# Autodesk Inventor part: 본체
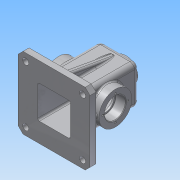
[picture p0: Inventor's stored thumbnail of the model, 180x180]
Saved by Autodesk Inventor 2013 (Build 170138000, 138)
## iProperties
Created: 2018-10
Part Number: 본체
Material: 알루미늄 6061
Document SubType Name: Modeling
Designer: Administrator
Density: 2.71 g/cm^3
Mass: 797.27 g
Surface Area: 899.907 cm^2
Volume: 294.196 cm^3
Author: Administrator
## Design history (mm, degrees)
sketch "스케치1"
  geometry: L1 (32.5, -32.5)-(-32.5, -32.5); L2 (-32.5, -32.5)-(-32.5, 32.5); L3 (-32.5, 32.5)-(32.5, 32.5); L4 (32.5, 32.5)-(32.5, -32.5); L5 (32.5, -32.5)-(-32.5, 32.5); L6 (-32.5, -32.5)-(32.5, 32.5); 1 further point
  constraints: 12 end point, 2 midpoint, 2 parallel, 1 horizontal, 1 perpendicular
  dimensions: "d0" = 65 distance of L2.end L3.end; "d1" = 65 distance of L1.end L2.end
extrude "돌출1" new body sketch "스케치1" distance "d2" = 55; taper "d4" = 0 deg; dims "d3" = 55, "d5" = 0
feature "쉘1" dims "d6" = 5
fillet "모깎기2" dims "d8" = 3
node "작업 평면1"
sketch "스케치2"
  geometry: C1 r 20 at (0, 0); 1 further point
  constraints: 1 centre point, 1 coincident
  dimensions: "d10" = 40 diameter of C1
extrude "돌출2" join sketch "스케치2" stored distance "d11" = 55; taper "d12" = 7 deg
hole "구멍1" diameter "d15" = 22.835; stored, may be unused: countersink angle "d19" = 90 deg, drill point angle "d21" = 118 deg; dims "d13" = 10, "d14" = 10, "d16" = 50, "d17" = 4, "d18" = 2, "d20" = 50
sketch "스케치3"
  geometry: L1 (-32.5, -32.5)-(32.5, -32.5) reference; L2 (32.5, -32.5)-(32.5, 32.5) reference; L3 (32.5, 32.5)-(-32.5, 32.5) reference; L4 (-32.5, 32.5)-(-32.5, -32.5) reference; L5 (60, -60)-(-60, -60); L6 (-60, -60)-(-60, 60); L7 (-60, 60)-(60, 60); L8 (60, 60)-(60, -60); L9 (60, -60)-(-60, 60); L10 (-60, -60)-(60, 60); A1 r 8 centre (24.5, -24.5) between (24.5, -32.5) and (32.5, -24.5) reference; A2 r 8 centre (24.5, 24.5) between (32.5, 24.5) and (24.5, 32.5) reference; A3 r 8 centre (-24.5, 24.5) between (-24.5, 32.5) and (-32.5, 24.5) reference; A4 r 8 centre (-24.5, -24.5) between (-32.5, -24.5) and (-24.5, -32.5) reference; 1 further point
  constraints: 12 end point, 2 midpoint, 2 parallel, 1 horizontal, 1 perpendicular
  dimensions: "d22" = 120 distance of L6.end L7.end; "d23" = 120 distance of L5.end L6.end
extrude "돌출3" join sketch "스케치3" distance "d24" = 10; taper "d25" = 0 deg
chamfer "모따기1" distance "d26" = 8; stored, may be unused: second distance "d27" = 2, angle "d28" = 45 deg
sketch "스케치4"
  geometry: L1 (-60, 52)-(-60, -52) reference; L2 (52, 60)-(-52, 60) reference; C1 r 5 at (-47.5, 47.5); 1 further point
  constraints: 1 centre point
  dimensions: "d29" = 10 diameter of C1; "d30" = 12.5 distance from line of C1.centre L1; "d31" = 12.5 distance from line of C1.centre L2
extrude "돌출4" cut sketch "스케치4" stored distance "d32" = 10; taper "d33" = 0 deg
sketch "스케치5"
  geometry: L1 (-19.5, -110)-(84.5, -110) reference; C1 r 27.5 at (32.5, -55); 1 further point
  constraints: 1 centre point, 1 coincident
  dimensions: "d34" = 55 diameter of C1; "d35" = 55 distance from line of L1 C1.centre
extrude "돌출5" join sketch "스케치5" distance "d36" = 15; taper "d37" = 0 deg
hole "구멍2" diameter "d40" = 30; stored, may be unused: countersink angle "d44" = 90 deg, drill point angle "d46" = 118 deg; dims "d38" = 10, "d39" = 10, "d41" = 50, "d42" = 35, "d43" = 17, "d45" = 50
sketch "스케치6"
  geometry: C1 r 17.5 at (0, 0) reference; 1 further point
  constraints: 1 vertical alignment
  dimensions: "d47" = 21 distance of C1.centre point (0, 21)
hole "구멍3" sketch "스케치6" at (0, 21) diameter "d48" = 3.242; stored, may be unused: countersink angle "d52" = 90 deg, drill point angle "d54" = 118 deg; dims "d49" = 8, "d50" = 35, "d51" = 17, "d53" = 10
chamfer "모따기2" distance "d58" = 1; stored, may be unused: second distance "d59" = 2, angle "d60" = 45 deg
fillet "모깎기3" dims "d61" = 8
sketch "스케치7"
  geometry: L1 (65, 11.418)-(50, 11.418) reference; L2 (50, 11.418)-(50, 24.5) reference; L3 (47, 27.5)-(-55, 27.5) reference; L4 (-55, 27.5)-(-55, 60) reference; L5 (-55, 60)-(-45, 60) reference; L6 (-45, 60)-(-45, 32.5) reference; L7 (-45, 32.5)-(47, 32.5) reference; L8 (55, 24.5)-(55, 21.228) reference; L9 (55, 21.228)-(65, 20) reference; L10 (65, 20)-(65, 11.418) reference; L11 (50, -11.418)-(65, -11.418) reference; L12 (65, -11.418)-(65, -20) reference; L13 (65, -20)-(55, -21.228) reference; L14 (55, -21.228)-(55, -24.5) reference; L15 (47, -32.5)-(-45, -32.5) reference; L16 (-45, -32.5)-(-45, -60) reference; L17 (-45, -60)-(-55, -60) reference; L18 (-55, -60)-(-55, -27.5) reference; L19 (-55, -27.5)-(47, -27.5) reference; L20 (50, -24.5)-(50, -11.418) reference; L21 (-45, 48)-(-13.889, 42.514); A1 r 3 centre (47, 24.5) between (50, 24.5) and (47, 27.5) reference; A2 r 8 centre (47, 24.5) between (55, 24.5) and (47, 32.5) reference; A3 r 8 centre (47, -24.5) between (47, -32.5) and (55, -24.5) reference; A4 r 3 centre (47, -24.5) between (47, -27.5) and (50, -24.5) reference; 1 further point
  constraints: 2 end point, 1 point on line
  dimensions: "d63" = 12 distance from line of L21.start L5; "d64" = 100 deg angle of L6 L21
feature "리브1" sketch "스케치7" dims "d65" = 1, "d66" = 10, "d67" = 0, "d68" = 0, "d69" = 1, "d70" = 1
fillet "모깎기5" dims "d71" = 3
fillet "모깎기6" dims "d72" = 3
sketch "스케치8"
  geometry: L1 (36.526, -21)-(37.5, -22.621) reference; L2 (37.5, -22.621)-(47.5, -22.621) reference; L3 (47.5, -22.621)-(47.5, -27.5) reference; L4 (47.5, -27.5)-(32.5, -27.5) reference; L5 (32.5, -27.5)-(32.5, -45) reference; L6 (32.5, -45)-(60, -45) reference; L7 (60, -45)-(60, -55) reference; L8 (60, -55)-(27.5, -55) reference; L9 (27.5, -55)-(27.5, -15) reference; L10 (27.5, -15)-(30.5, -15) reference; L11 (30.5, -15)-(30.5, -17.5) reference; L12 (30.5, -17.5)-(46.5, -17.5) reference; L13 (46.5, -17.5)-(47.5, -18.5) reference; L14 (47.5, -18.5)-(47.5, -19.379) reference; L15 (47.5, -19.379)-(37.5, -19.379) reference; L16 (37.5, -19.379)-(36.526, -21) reference; L17 (37.5, 22.621)-(36.526, 21) reference; L18 (36.526, 21)-(37.5, 19.379) reference; L19 (37.5, 19.379)-(47.5, 19.379) reference; L20 (47.5, 19.379)-(47.5, 18.5) reference; L21 (47.5, 18.5)-(46.5, 17.5) reference; L22 (46.5, 17.5)-(30.5, 17.5) reference; L23 (30.5, 17.5)-(30.5, 15) reference; L24 (30.5, 15)-(27.5, 15) reference; L25 (27.5, 15)-(27.5, 47) reference; L26 (24.5, 50)-(11.418, 50) reference; L27 (11.418, 50)-(11.418, 65) reference; L28 (11.418, 65)-(20, 65) reference; L29 (20, 65)-(21.228, 55) reference; L30 (21.228, 55)-(24.5, 55) reference; L31 (32.5, 47)-(32.5, 27.5) reference; L32 (32.5, 27.5)-(47.5, 27.5) reference; L33 (47.5, 27.5)-(47.5, 22.621) reference; L34 (47.5, 22.621)-(37.5, 22.621) reference; L35 (-37.5, -22.621)-(-36.526, -21) reference; L36 (-36.526, -21)-(-37.5, -19.379) reference; L37 (-37.5, -19.379)-(-47.5, -19.379) reference; L38 (-47.5, -19.379)-(-47.5, -18.5) reference; L39 (-47.5, -18.5)-(-46.5, -17.5) reference; L40 (-46.5, -17.5)-(-30.5, -17.5) reference; L41 (-30.5, -17.5)-(-30.5, -15) reference; L42 (-30.5, -15)-(-27.5, -15) reference; L43 (-27.5, -15)-(-27.5, -55) reference; L44 (-27.5, -55)-(-60, -55) reference; L45 (-60, -55)-(-60, -45) reference; L46 (-60, -45)-(-32.5, -45) reference; L47 (-32.5, -45)-(-32.5, -27.5) reference; L48 (-32.5, -27.5)-(-47.5, -27.5) reference; L49 (-47.5, -27.5)-(-47.5, -22.621) reference; L50 (-47.5, -22.621)-(-37.5, -22.621) reference; L51 (-36.526, 21)-(-37.5, 22.621) reference; L52 (-37.5, 22.621)-(-47.5, 22.621) reference; L53 (-47.5, 22.621)-(-47.5, 27.5) reference; L54 (-47.5, 27.5)-(-32.5, 27.5) reference; L55 (-32.5, 27.5)-(-32.5, 47) reference; L56 (-24.5, 55)-(-21.228, 55) reference; L57 (-21.228, 55)-(-20, 65) reference; L58 (-20, 65)-(-11.418, 65) reference; L59 (-11.418, 65)-(-11.418, 50) reference; L60 (-11.418, 50)-(-24.5, 50) reference; L61 (-27.5, 47)-(-27.5, 15) reference; L62 (-27.5, 15)-(-30.5, 15) reference; L63 (-30.5, 15)-(-30.5, 17.5) reference; L64 (-30.5, 17.5)-(-46.5, 17.5) reference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; A1 r 3 centre (24.5, 47) between (27.5, 47) and (24.5, 50) reference; A2 r 8 centre (24.5, 47) between (32.5, 47) and (24.5, 55) reference; A3 r 8 centre (-24.5, 47) between (-24.5, 55) and (-32.5, 47) reference; A4 r 3 centre (-24.5, 47) between (-24.5, 50) and (-27.5, 47) reference; 1 further point
  constraints: 2 end point, 1 perpendicular, 1 point on line
  dimensions: "d74" = 15 distance between parallel lines of L43 L69
feature "리브2" sketch "스케치8" dims "d75" = 1, "d76" = 6, "d77" = 0, "d78" = 0, "d79" = 1, "d80" = 1
fillet "모깎기8" dims "d82" = 3
fillet "모깎기9" dims "d83" = 3
fillet "모깎기10" dims "d84" = 3
fillet "모깎기11" dims "d85" = 3
sketch "스케치9"
  geometry: L1 (-8, 0)-(-8, -92) reference; L2 (4.5, 18)-(44.5, 18) reference; 1 further point
  constraints: 1 other
  dimensions: "d86" = 32.5 distance from line of point (24.5, -8) L1; "d87" = 26 distance from line of point (24.5, -8) L2
feature "엠보싱1" sketch "스케치9" dims "d88" = 0.5, "d89" = 0
fillet "모깎기12" dims "d90" = 0.3
fillet "모깎기13" dims "d91" = 3
fillet "모깎기14" dims "d92" = 1
node "솔리드1"
mirror "대칭1"
mirror "대칭2"
pattern_circular "원형 패턴1" dims angle "d56" = 360 deg
mirror "대칭3"
mirror "대칭4"
mirror "대칭5"
node "절단 모서리 투영1"
node "절단 모서리 투영2"
other parameters: "d9" = 65
